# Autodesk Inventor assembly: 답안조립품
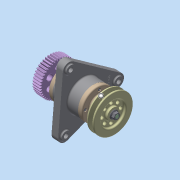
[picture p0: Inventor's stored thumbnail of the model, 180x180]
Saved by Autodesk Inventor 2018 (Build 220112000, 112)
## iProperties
Created: 2023-04
Part Number: 답안조립품
Material: 일반
Document SubType Name: Assembly
Designer: home
Author: home
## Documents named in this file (11)
- C:\Users\home\Desktop\730407V1007\답안조립품.iam
- C:\Users\home\Desktop\730407V1007\본체.ipt
- C:\Users\home\Desktop\730407V1007\6각 플랜지 너트 M10.ipt
- C:\Users\home\Desktop\730407V1007\v-벨트풀리.ipt
- C:\Users\home\Desktop\730407V1007\묻힘키 5x5x16.ipt
- C:\Users\home\Desktop\730407V1007\베어링 6204.ipt
- C:\Users\home\Desktop\730407V1007\볼트 M4 x 12.ipt
- C:\Users\home\Desktop\730407V1007\스퍼기어.ipt
- C:\Users\home\Desktop\730407V1007\오일 실 20 32 8.ipt
- C:\Users\home\Desktop\730407V1007\축.ipt
- C:\Users\home\Desktop\730407V1007\커버.ipt
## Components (3 placed, 2 different names)
1. 6각 플랜지 너트 M10:1
2. v-벨트풀리:1
3. 6각 플랜지 너트 M10:2
